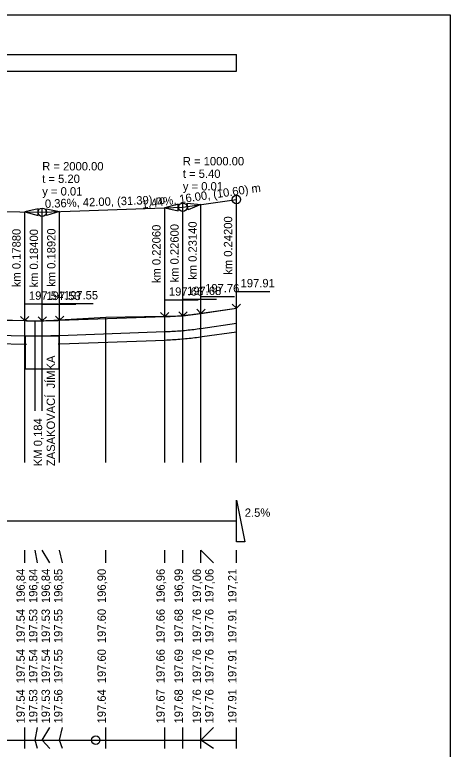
# Model space of a CAD drawing. Extents: x -24.9 to 20.5, y -71.8 to 17.3.
# Drawn here: x 7.53 to 20.54, y -4.65 to 17.31 of the extents above; entities that cross this region are included whole.
import ezdxf

# ---------------------------------------------------------------- set-up
doc = ezdxf.new("R2010")
doc.units = 0
for name, color, linetype in [('Implicitní', 7, 'Continuous'), ('KONSTRUKCE_L', 7, 'Continuous'), ('KOTY_L', 7, 'Continuous'), ('KOTY_N', 7, 'Continuous'), ('KOTY_S', 7, 'Continuous'), ('KOTY_T', 7, 'Continuous'), ('KOTY_VP', 7, 'Continuous'), ('Nová vrstva (0)', 7, 'Continuous'), ('PR_SKLON_L', 7, 'Continuous'), ('PR_SKLON_T', 7, 'Continuous'), ('ROVINA_L', 7, 'Continuous'), ('ROVINA_O', 7, 'Continuous'), ('SKLON_POMERY', 7, 'Continuous'), ('TABULKY_L', 7, 'Continuous'), ('TEREN_L', 7, 'Continuous'), ('V_POLYGON', 7, 'Continuous'), ('V_POLYGON_ZO', 7, 'Continuous')]:
    doc.layers.add(name, color=color, linetype=linetype)

msp = doc.modelspace()

# ---------------------------------------------------------------- linework, layer by layer
at = {"layer": 'Implicitní'}
msp.add_lwpolyline([(-24.886, 17.307), (20.536, 17.307), (20.536, -12.393), (-24.886, -12.393)], close=True, dxfattribs=at)
at = {"layer": 'KONSTRUKCE_L'}
for p, q in [((12.872, 7.901), (12.926, 7.908)), ((12.926, 7.908), (12.98, 7.915)), ((12.98, 7.915), (13.034, 7.923)), ((13.034, 7.923), (13.088, 7.93)), ((13.088, 7.93), (14.148, 8.082)), ((3.817, 7.776), (7.827, 7.711)), ((7.827, 7.711), (7.879, 7.71)), ((7.879, 7.71), (7.931, 7.71)), ((7.931, 7.71), (7.983, 7.709)), ((7.983, 7.709), (8.035, 7.709)), ((8.035, 7.709), (8.087, 7.708)), ((8.087, 7.708), (8.139, 7.708)), ((8.139, 7.708), (8.191, 7.708)), ((8.191, 7.708), (8.243, 7.709)), ((8.243, 7.709), (8.295, 7.709)), ((8.295, 7.709), (8.348, 7.709)), ((8.348, 7.709), (8.4, 7.71)), ((8.4, 7.71), (8.452, 7.711)), ((8.452, 7.711), (8.504, 7.711)), ((8.504, 7.711), (8.556, 7.712)), ((8.556, 7.712), (8.608, 7.713)), ((8.608, 7.713), (8.66, 7.715)), ((8.66, 7.715), (8.712, 7.716)), ((8.712, 7.716), (8.764, 7.718)), ((8.764, 7.718), (8.816, 7.719)), ((8.816, 7.719), (8.868, 7.721)), ((8.868, 7.721), (12.007, 7.833)), ((12.007, 7.833), (12.061, 7.835)), ((12.061, 7.835), (12.115, 7.838)), ((12.115, 7.838), (12.169, 7.84)), ((12.169, 7.84), (12.223, 7.843)), ((12.223, 7.843), (12.277, 7.847)), ((12.277, 7.847), (12.331, 7.85)), ((12.331, 7.85), (12.385, 7.854)), ((12.385, 7.854), (12.439, 7.858)), ((12.439, 7.858), (12.494, 7.862)), ((12.494, 7.862), (12.548, 7.867)), ((12.548, 7.867), (12.602, 7.872)), ((12.602, 7.872), (12.656, 7.877)), ((12.656, 7.877), (12.71, 7.883)), ((12.71, 7.883), (12.764, 7.889)), ((12.764, 7.889), (12.818, 7.895)), ((12.818, 7.895), (12.872, 7.901))]:
    msp.add_line(p, q, dxfattribs=at)
at = {"layer": 'KOTY_L'}
for p, q in [((13.088, 3.923), (13.088, 8.38)), ((13.088, 3.923), (13.088, 8.38)), ((14.148, 3.923), (14.148, 8.533)), ((7.827, 3.923), (7.827, 8.164)), ((8.139, 5.468), (8.139, 8.157)), ((8.348, 5.468), (8.348, 8.152)), ((8.868, 3.923), (8.868, 8.183)), ((10.248, 3.923), (10.248, 8.263)), ((12.007, 3.923), (12.007, 8.293)), ((12.548, 3.923), (12.548, 8.303)), ((7.827, 0.923), (7.827, 1.298)), ((8.202, 0.923), (8.139, 1.298)), ((8.577, 0.923), (8.348, 1.298)), ((8.952, 0.923), (8.868, 1.298)), ((10.248, 0.923), (10.248, 1.298)), ((12.007, 0.923), (12.007, 1.298)), ((12.548, 0.923), (12.548, 1.298)), ((13.088, 0.923), (13.088, 1.298)), ((13.463, 0.923), (13.088, 1.298)), ((14.148, 0.923), (14.148, 1.298)), ((7.827, -2.678), (7.827, -2.678)), ((8.202, -2.678), (8.202, -2.678)), ((8.577, -2.678), (8.577, -2.678)), ((8.952, -2.678), (8.952, -2.678)), ((10.248, -2.678), (10.248, -2.678)), ((12.007, -2.678), (12.007, -2.678)), ((12.548, -2.678), (12.548, -2.678)), ((13.088, -2.678), (13.088, -2.678)), ((13.463, -2.678), (13.463, -2.678)), ((14.148, -2.678), (14.148, -2.678)), ((7.827, -4.378), (7.827, -4.003)), ((8.139, -4.378), (8.202, -4.003)), ((8.348, -4.378), (8.577, -4.003)), ((8.868, -4.378), (8.952, -4.003)), ((10.248, -4.378), (10.248, -4.003)), ((12.007, -4.378), (12.007, -4.003)), ((12.548, -4.378), (12.548, -4.003)), ((13.088, -4.378), (13.088, -4.003)), ((13.088, -4.378), (13.463, -4.003)), ((14.148, -4.378), (14.148, -4.003))]:
    msp.add_line(p, q, dxfattribs=at)
at = {"layer": 'KOTY_S'}
for p, q in [((7.827, -4.628), (7.827, -4.378)), ((8.202, -4.628), (8.139, -4.378)), ((8.577, -4.628), (8.348, -4.378)), ((8.952, -4.628), (8.868, -4.378)), ((10.248, -4.628), (10.248, -4.378)), ((12.007, -4.628), (12.007, -4.378)), ((12.548, -4.628), (12.548, -4.378)), ((13.088, -4.628), (13.088, -4.378)), ((13.463, -4.628), (13.088, -4.378)), ((14.148, -4.628), (14.148, -4.378))]:
    msp.add_line(p, q, dxfattribs=at)
at = {"layer": 'Nová vrstva (0)'}
for p, q in [((13.123, 7.683), (14.148, 7.83)), ((3.813, 7.526), (7.823, 7.461)), ((8.825, 7.469), (8.877, 7.471)), ((8.877, 7.471), (12.016, 7.583)), ((12.017, 7.583), (12.071, 7.585)), ((12.072, 7.586), (12.126, 7.588)), ((12.128, 7.588), (12.182, 7.591)), ((12.183, 7.591), (12.237, 7.594)), ((12.238, 7.594), (12.292, 7.597)), ((12.294, 7.597), (12.348, 7.601)), ((12.349, 7.601), (12.403, 7.604)), ((12.404, 7.605), (12.458, 7.609)), ((12.46, 7.609), (12.514, 7.613)), ((12.515, 7.613), (12.569, 7.618)), ((12.571, 7.618), (12.625, 7.623)), ((12.626, 7.623), (12.68, 7.629)), ((12.681, 7.629), (12.735, 7.634)), ((12.737, 7.634), (12.791, 7.64)), ((12.792, 7.64), (12.846, 7.647)), ((12.847, 7.647), (12.901, 7.653)), ((12.903, 7.653), (12.957, 7.66)), ((12.958, 7.66), (13.012, 7.667)), ((13.013, 7.667), (13.067, 7.675)), ((13.069, 7.675), (13.123, 7.683)), ((7.823, 7.461), (7.875, 7.46))]:
    msp.add_line(p, q, dxfattribs=at)
msp.add_lwpolyline([(7.848, 7.709), (8.848, 7.709), (8.848, 6.709), (7.848, 6.709)], close=True, dxfattribs=at)
at = {"layer": 'PR_SKLON_L'}
msp.add_line((-10.052, 2.173), (14.148, 2.173), dxfattribs=at)
msp.add_lwpolyline([(14.148, 2.173), (14.148, 2.798), (14.398, 1.548), (14.148, 1.548)], close=True, dxfattribs=at)
at = {"layer": 'ROVINA_L'}
msp.add_line((-10.052, -4.378), (14.148, -4.378), dxfattribs=at)
at = {"layer": 'ROVINA_O'}
msp.add_circle((9.948, -4.378), 0.125, dxfattribs=at)
at = {"layer": 'SKLON_POMERY'}
for p, q in [((14.148, 11.783), (14.148, 11.908)), ((12.548, 11.553), (14.148, 11.783)), ((12.548, 11.553), (12.548, 11.678)), ((14.148, 8.533), (14.148, 11.783)), ((3.448, 11.482), (8.348, 11.402)), ((8.348, 11.402), (12.548, 11.553)), ((8.348, 11.402), (8.348, 11.527)), ((8.868, 8.171), (8.868, 11.421)), ((12.007, 8.283), (12.007, 11.533)), ((12.548, 8.303), (12.548, 11.553)), ((13.088, 8.38), (13.088, 11.63)), ((7.827, 8.161), (7.827, 11.411)), ((8.348, 8.152), (8.348, 11.402))]:
    msp.add_line(p, q, dxfattribs=at)
for points in [[(12.007, 11.533), (12.411, 11.448), (12.404, 11.647), (12.007, 11.533)], [(13.088, 11.63), (12.706, 11.474), (12.678, 11.672), (13.088, 11.63)], [(7.827, 11.411), (8.225, 11.304), (8.229, 11.504), (7.827, 11.411)], [(8.868, 11.421), (8.472, 11.307), (8.465, 11.507), (8.868, 11.421)]]:
    msp.add_lwpolyline(points, close=True, dxfattribs=at)
for points in [[(14.023, 8.658), (14.148, 8.533), (14.273, 8.658), (14.148, 8.533), (14.148, 9.033), (15.148, 9.033)], [(12.423, 8.428), (12.548, 8.303), (12.673, 8.428), (12.548, 8.303), (12.548, 8.803), (13.548, 8.803)], [(12.963, 8.505), (13.088, 8.38), (13.213, 8.505), (13.088, 8.38), (13.088, 8.88), (14.088, 8.88)], [(7.702, 8.286), (7.827, 8.161), (7.952, 8.286), (7.827, 8.161), (7.827, 8.661), (8.827, 8.661)], [(8.223, 8.277), (8.348, 8.152), (8.473, 8.277), (8.348, 8.152), (8.348, 8.652), (9.348, 8.652)], [(8.743, 8.296), (8.868, 8.171), (8.993, 8.296), (8.868, 8.171), (8.868, 8.671), (9.868, 8.671)], [(11.882, 8.408), (12.007, 8.283), (12.132, 8.408), (12.007, 8.283), (12.007, 8.783), (13.007, 8.783)]]:
    msp.add_lwpolyline(points, dxfattribs=at)
for centre in [(14.148, 11.783), (12.548, 11.553), (8.348, 11.402)]:
    msp.add_circle(centre, 0.125, dxfattribs=at)
at = {"layer": 'TABULKY_L'}
for p, q in [((-10.052, 16.122), (14.148, 16.122)), ((14.148, 15.622), (14.148, 16.122)), ((-10.052, 15.622), (14.148, 15.622))]:
    msp.add_line(p, q, dxfattribs=at)
at = {"layer": 'TEREN_L'}
for p, q in [((12.548, 8.303), (14.148, 8.533)), ((6.148, 8.203), (8.348, 8.152)), ((8.348, 8.152), (10.248, 8.263)), ((10.248, 8.263), (12.548, 8.303))]:
    msp.add_line(p, q, dxfattribs=at)
at = {"layer": 'V_POLYGON'}
for p, q in [((13.088, 8.38), (14.148, 8.533)), ((3.817, 8.226), (7.827, 8.161)), ((8.868, 8.171), (12.007, 8.283))]:
    msp.add_line(p, q, dxfattribs=at)
for points in [[(12.007, 8.283), (12.061, 8.285), (12.115, 8.288), (12.169, 8.29), (12.223, 8.293), (12.277, 8.297), (12.331, 8.3), (12.385, 8.304), (12.439, 8.308), (12.494, 8.312), (12.548, 8.317), (12.602, 8.322), (12.656, 8.327), (12.71, 8.333), (12.764, 8.339), (12.818, 8.345), (12.872, 8.351), (12.926, 8.358), (12.98, 8.365), (13.034, 8.373), (13.088, 8.38)], [(7.827, 8.161), (7.879, 8.16), (7.931, 8.16), (7.983, 8.159), (8.035, 8.159), (8.087, 8.158), (8.139, 8.158), (8.191, 8.158), (8.243, 8.159), (8.295, 8.159), (8.348, 8.159), (8.4, 8.16), (8.452, 8.161), (8.504, 8.161), (8.556, 8.162), (8.608, 8.163), (8.66, 8.165), (8.712, 8.166), (8.764, 8.168), (8.816, 8.169), (8.868, 8.171)]]:
    msp.add_lwpolyline(points, dxfattribs=at)
at = {"layer": 'V_POLYGON_ZO'}
for p, q in [((12.548, 8.303), (13.088, 8.38)), ((7.827, 8.161), (8.348, 8.152)), ((8.348, 8.152), (8.868, 8.171)), ((12.007, 8.283), (12.548, 8.303))]:
    msp.add_line(p, q, dxfattribs=at)

# ---------------------------------------------------------------- texts
at = {"layer": 'KOTY_N'}
for s, p in [('197.54', (7.827, -2.678)), ('197.54', (8.202, -2.678)), ('197.54', (8.577, -2.678)), ('197.55', (8.952, -2.678)), ('197.60', (10.248, -2.678)), ('197.66', (12.007, -2.678)), ('197.69', (12.548, -2.678)), ('197.76', (13.088, -2.678)), ('197.76', (13.463, -2.678)), ('197.91', (14.148, -2.678))]:
    msp.add_text(s, height=0.25, rotation=90, dxfattribs=at).set_placement(p)
at = {"layer": 'KOTY_T'}
for s, p in [('197.54', (7.827, -3.878)), ('197.53', (8.202, -3.878)), ('197.53', (8.577, -3.878)), ('197.56', (8.952, -3.878)), ('197.64', (10.248, -3.878)), ('197.67', (12.007, -3.878)), ('197.68', (12.548, -3.878)), ('197.76', (13.088, -3.878)), ('197.76', (13.463, -3.878)), ('197.91', (14.148, -3.878))]:
    msp.add_text(s, height=0.25, rotation=90, dxfattribs=at).set_placement(p)
at = {"layer": 'KOTY_VP'}
for s, p in [('197.54', (7.827, -1.478)), ('197.53', (8.202, -1.478)), ('197.53', (8.577, -1.478)), ('197.55', (8.952, -1.478)), ('197.60', (10.248, -1.478)), ('197.66', (12.007, -1.478)), ('197.68', (12.548, -1.478)), ('197.76', (13.088, -1.478)), ('197.76', (13.463, -1.478)), ('197.91', (14.148, -1.478))]:
    msp.add_text(s, height=0.25, rotation=90, dxfattribs=at).set_placement(p)
at = {"layer": 'Nová vrstva (0)'}
for s, p in [('ZASAKOVACÍ  JÍMKA', (8.729, 3.812)), ('KM 0,184', (8.345, 3.812)), ('196,84', (7.827, -0.278)), ('196,84', (8.202, -0.278)), ('196,84', (8.577, -0.278)), ('196,85', (8.952, -0.278)), ('196,90', (10.248, -0.278)), ('196,96', (12.007, -0.278)), ('196,99', (12.548, -0.278)), ('197,06', (13.088, -0.278)), ('197,06', (13.463, -0.278)), ('197,21', (14.148, -0.278))]:
    msp.add_text(s, height=0.25, rotation=90, dxfattribs=at).set_placement(p)
at = {"layer": 'PR_SKLON_T'}
msp.add_text('2.5%', height=0.25, dxfattribs=at).set_placement((14.398, 2.298))
at = {"layer": 'SKLON_POMERY'}
for s, p in [('R = 1000.00', (12.548, 12.803)), ('R = 2000.00', (8.348, 12.652)), ('t = 5.20', (8.348, 12.277)), ('t = 5.40', (12.548, 12.428)), ('y = 0.01', (12.548, 12.053)), ('y = 0.01', (8.348, 11.902)), ('197.76', (13.213, 9.005)), ('197.91', (14.273, 9.158)), ('197.54', (7.952, 8.786)), ('197.53', (8.473, 8.777)), ('197.55', (8.993, 8.796)), ('197.66', (12.132, 8.908)), ('197.68', (12.673, 8.928))]:
    msp.add_text(s, height=0.25, dxfattribs=at).set_placement(p)
for s, rotation, p in [('1.44%, 16.00, (10.60) m', 8.1802, (11.338, 11.507)), ('0.36%, 42.00, (31.39) m', 2.0454, (8.432, 11.531)), ('km 0.24200', 90, (14.023, 9.533)), ('km 0.22060', 90, (11.882, 9.283)), ('km 0.22600', 90, (12.423, 9.303)), ('km 0.23140', 90, (12.963, 9.38)), ('km 0.17880', 90, (7.702, 9.161)), ('km 0.18400', 90, (8.223, 9.152)), ('km 0.18920', 90, (8.743, 9.171))]:
    msp.add_text(s, height=0.25, rotation=rotation, dxfattribs=at).set_placement(p)

doc.saveas('drawing.dxf')
